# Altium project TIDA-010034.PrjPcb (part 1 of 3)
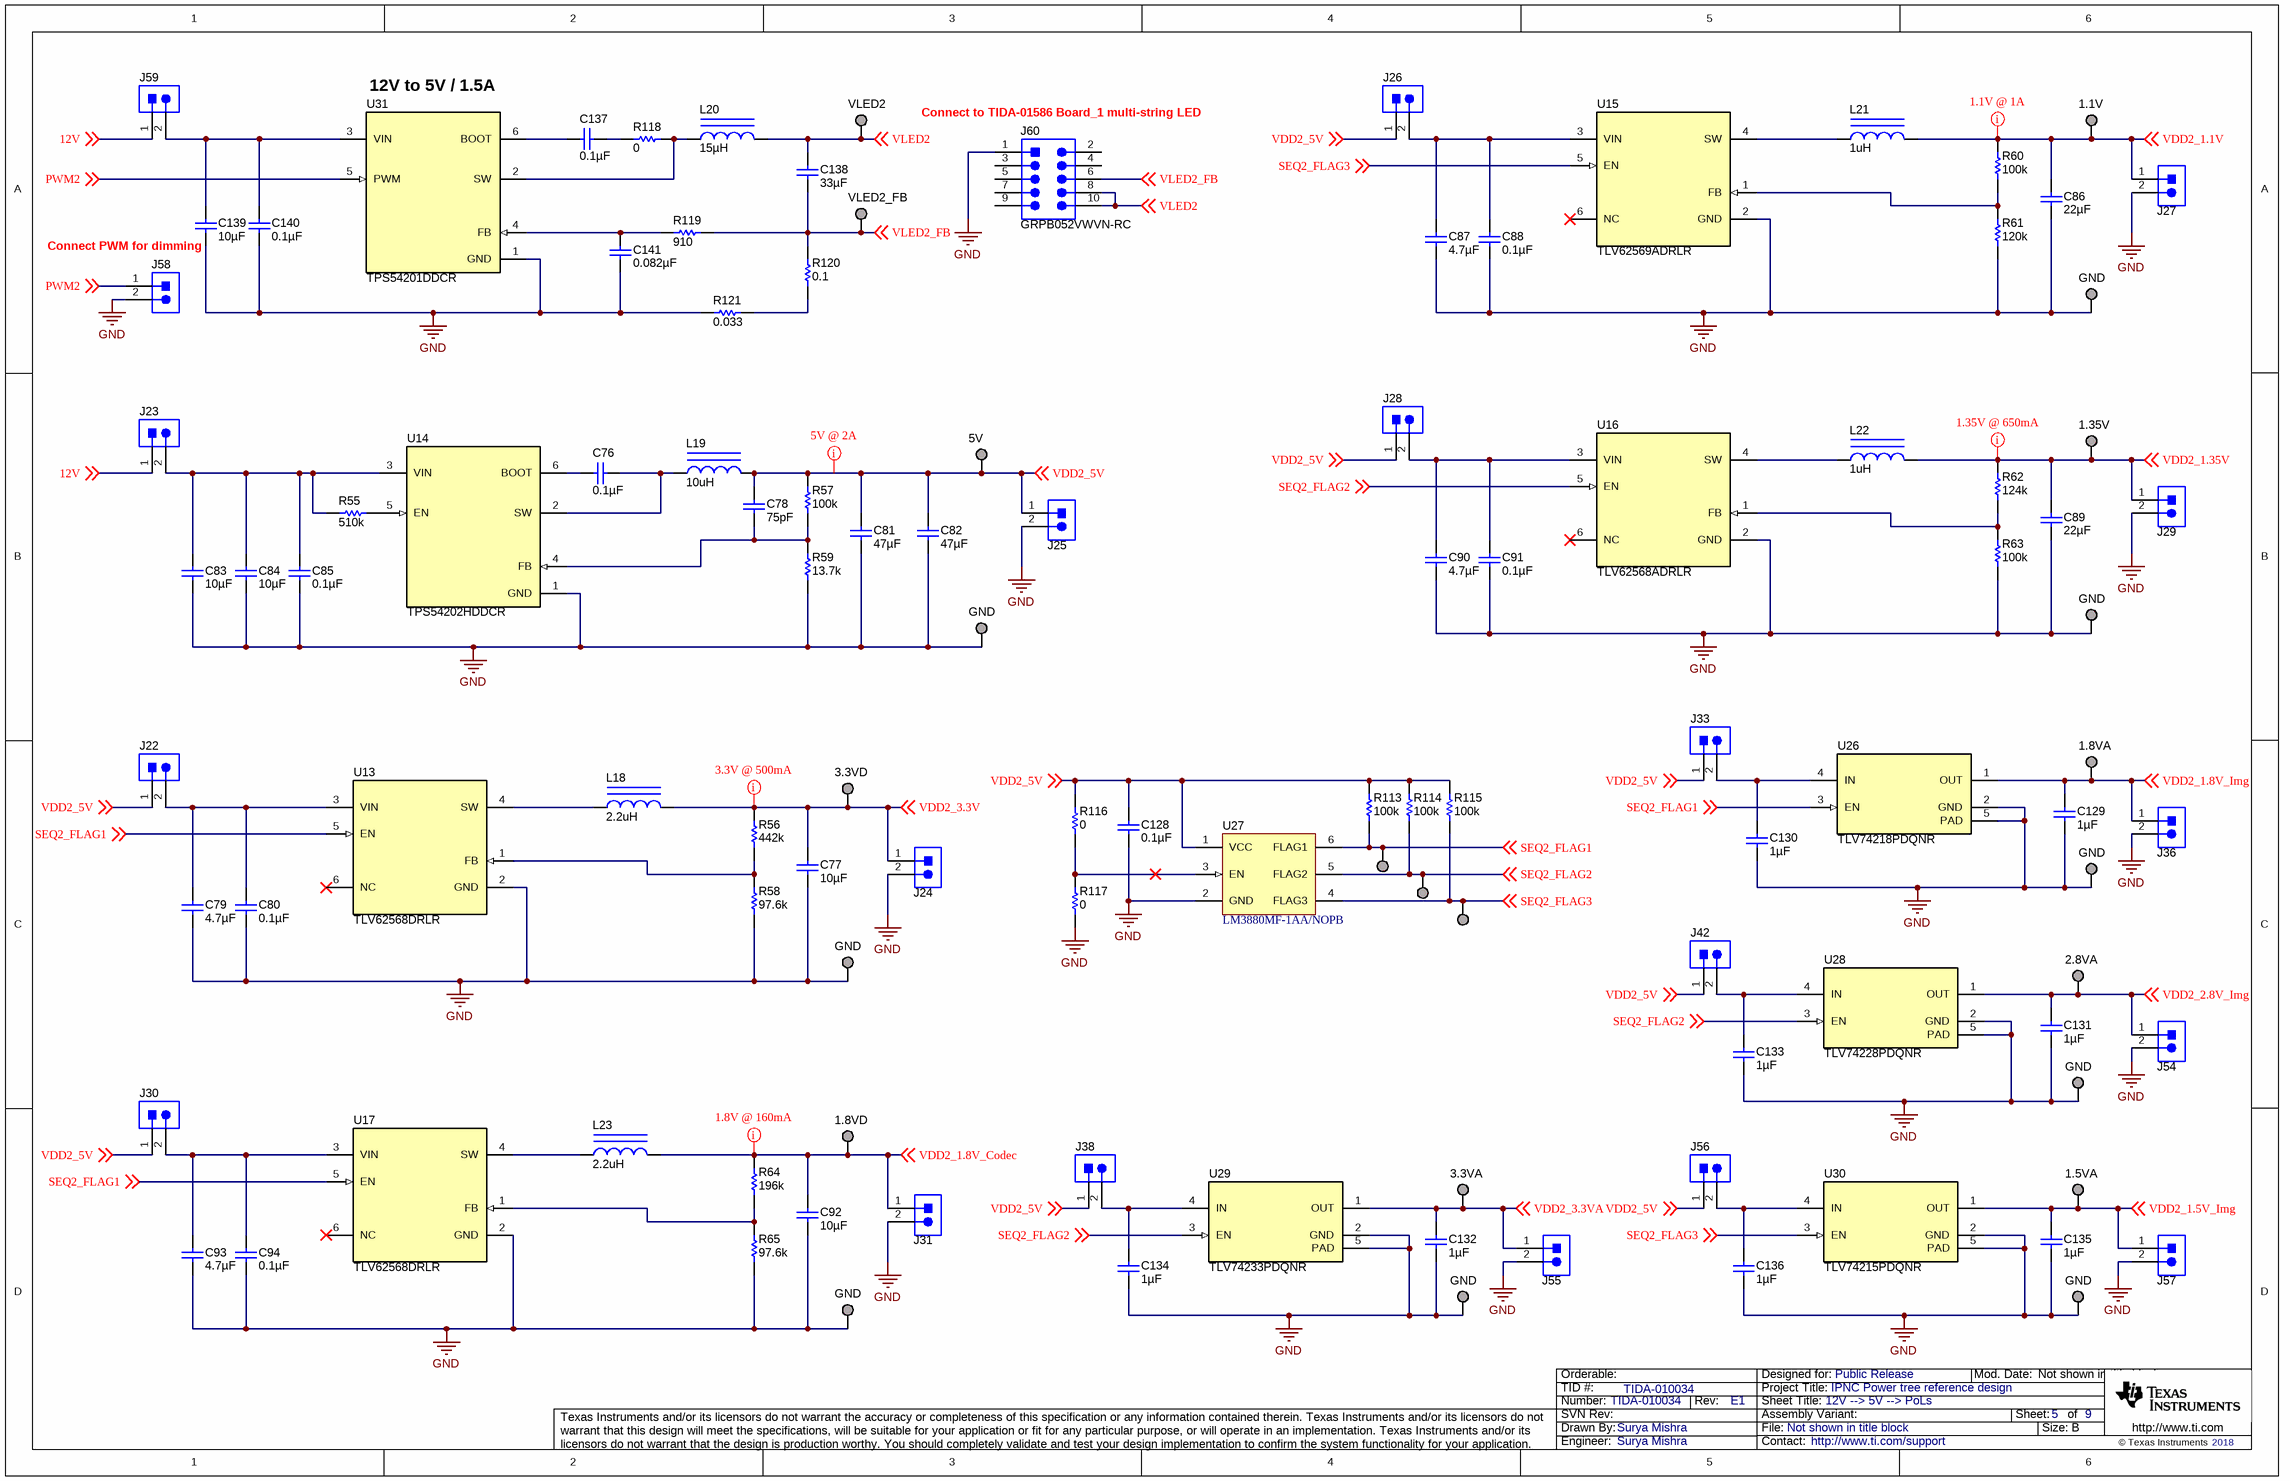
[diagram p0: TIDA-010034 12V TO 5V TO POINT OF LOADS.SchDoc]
CopyrightYear: 2018; PCB_Layout: Surya Mishra; PCB_Rev: E1; PRJ_Customer: Public Release; PRJ_Engineer: Surya Mishra; PRJ_Number: TIDA-010034; PRJ_Title: IPNC Power tree reference design; SCH_Rev: E1; TechSupport: http://www.ti.com/support; TID: TIDA-010034
9 sheets, 485 parts. Net scope: flat (ports and power ports of the same name join across sheets).
Board file: TIDA-010034 PCB.PcbDoc
Sheets:
  TIDA-010034 12V TO 5V TO POINT OF LOADS.SchDoc
  TIDA-010034 12V To POINT OF LOADS.SchDoc
  TIDA-010034 PoE INPUT.SchDoc
  TIDA-010034 USB INPUT.SchDoc
  TIDA-010034 Block Diagram.SchDoc
  TIDA-010034 TPS23755 PD FRONT-END.SchDoc
  TIDA-010034 MSP430.SchDoc
  TIDA-010034 DP83825 ETHERNET PHY.SchDoc
  TIDA-010034 Hardware.SchDoc

## Sheet TIDA-010034 12V TO 5V TO POINT OF LOADS.SchDoc: 12V --> 5V --> PoLs
size 431 x 279 mm; Date: Not shown in title block; ApprovedBy: Not shown in title block; CheckedBy: Not shown in title block; Author: Not shown in title block; CompanyName: Not shown in title block; DrawnBy: Surya Mishra; Engineer: Surya Mishra; Organization: Not shown in title block; Address1: Not shown in title block; Address2: Not shown in title block; Address3: Not shown in title block; Address4: Not shown in title block; DocumentNumber: 1; Revision: E1; SheetNumber: 5; SheetTotal: 9; PageSetup: Record=PageOptions¦CenterHorizontal=True¦CenterVertical=True¦PrintScale=1.00¦XCorrection=1.00¦YCorrection=1.00¦PrintKind=0¦BorderSize=5000000¦LeftOffset=0¦BottomOffset=0¦Orientation=2¦PaperLength=1000¦PaperWidth=1000¦Scale=100¦PaperSource=15¦PrintQuality=600¦MediaType=1¦DitherType=10¦PaperKind=Letter¦PrintScaleMode=1

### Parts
(Parts that share a designator on the sheet are numbered #1, #2 ... from top to bottom, then left to right.)
1.1V#1  TESTPOINT  [Keystone_5019]  (value not drawn)
1.5VA#1  TESTPOINT  [Keystone_5019]  (value not drawn)
1.8VA#1  TESTPOINT  [Keystone_5019]  (value not drawn)
1.8VD#1  TESTPOINT  [Keystone_5019]  (value not drawn)
1.35V#1  TESTPOINT  [Keystone_5019]  (value not drawn)
2.8VA#1  TESTPOINT  [Keystone_5019]  (value not drawn)
3.3VA#1  TESTPOINT  [Keystone_5019]  (value not drawn)
3.3VD  TESTPOINT  [Keystone_5019]  (value not drawn)
5V#1  TESTPOINT  [Keystone_5019]  (value not drawn)
C76  ValueDisplayed: 0.1µF  [0402]  (hidden comment: GRM155R71A104KA01D)
C77  ValueDisplayed: 10µF  [0805_HV]  (hidden comment: GRM21BR71A106ME51L)
C78  ValueDisplayed: 75pF  [0402]  (hidden comment: GRM1555C1H750JA01D)
C79  ValueDisplayed: 4.7µF  [0805_HV]  (hidden comment: GRM21BR71C475KA73L)
C80  ValueDisplayed: 0.1µF  [0402]  (hidden comment: GRM155R71E104KE14D)
C81  ValueDisplayed: 47µF  [1210_270]  (hidden comment: GRM32ER61C476ME15L)
C82  ValueDisplayed: 47µF  [1210_270]  (hidden comment: GRM32ER61C476ME15L)
C83  ValueDisplayed: 10µF  [0603]  (hidden comment: GRM188R61E106MA73D)
C84  ValueDisplayed: 10µF  [0603]  (hidden comment: GRM188R61E106MA73D)
C85  ValueDisplayed: 0.1µF  [0402]  (hidden comment: GRM155R71E104KE14D)
C86  ValueDisplayed: 22µF  [1206_180]  (hidden comment: GRM31CR61C226ME15L)
C87  ValueDisplayed: 4.7µF  [0805_HV]  (hidden comment: GRM21BR71C475KA73L)
C88  ValueDisplayed: 0.1µF  [0402]  (hidden comment: GRM155R71E104KE14D)
C89  ValueDisplayed: 22µF  [1206_180]  (hidden comment: GRM31CR61C226ME15L)
C90  ValueDisplayed: 4.7µF  [0805_HV]  (hidden comment: GRM21BR71C475KA73L)
C91  ValueDisplayed: 0.1µF  [0402]  (hidden comment: GRM155R71E104KE14D)
C92  ValueDisplayed: 10µF  [0805_HV]  (hidden comment: GRM21BR71A106ME51L)
C93  ValueDisplayed: 4.7µF  [0805_HV]  (hidden comment: GRM21BR71C475KA73L)
C94  ValueDisplayed: 0.1µF  [0402]  (hidden comment: GRM155R71E104KE14D)
C128  ValueDisplayed: 0.1µF  [0402]  (hidden comment: GRM155R71E104KE14D)
C129  ValueDisplayed: 1µF  [0603]  (hidden comment: GRM188R71C105KA12D)
C130  ValueDisplayed: 1µF  [0603]  (hidden comment: GRM188R71C105KA12D)
C131  ValueDisplayed: 1µF  [0603]  (hidden comment: GRM188R71C105KA12D)
C132  ValueDisplayed: 1µF  [0603]  (hidden comment: GRM188R71C105KA12D)
C133  ValueDisplayed: 1µF  [0603]  (hidden comment: GRM188R71C105KA12D)
C134  ValueDisplayed: 1µF  [0603]  (hidden comment: GRM188R71C105KA12D)
C135  ValueDisplayed: 1µF  [0603]  (hidden comment: GRM188R71C105KA12D)
C136  ValueDisplayed: 1µF  [0603]  (hidden comment: GRM188R71C105KA12D)
C137  ValueDisplayed: 0.1µF  [0402]  (hidden comment: GRM155R71A104KA01D)
C138  ValueDisplayed: 33µF  [1206_180]  (hidden comment: C3216X5R1E336M160AC)
C139  ValueDisplayed: 10µF  [0603]  (hidden comment: GRM188R61E106MA73D)
C140  ValueDisplayed: 0.1µF  [0402]  (hidden comment: GRM155R71E104KE14D)
C141  ValueDisplayed: 0.082µF  [0402]  (hidden comment: GRM155R71A823KA01D)
GND#1  TESTPOINT  [Keystone_5019]  (value not drawn)
GND#2  TESTPOINT  [Keystone_5019]  (value not drawn)
GND#3  TESTPOINT  [Keystone_5019]  (value not drawn)
GND#4  TESTPOINT  [Keystone_5019]  (value not drawn)
GND#5  TESTPOINT  [Keystone_5019]  (value not drawn)
GND#6  TESTPOINT  [Keystone_5019]  (value not drawn)
GND#7  TESTPOINT  [Keystone_5019]  (value not drawn)
GND#8  TESTPOINT  [Keystone_5019]  (value not drawn)
GND#9  TESTPOINT  [Keystone_5019]  (value not drawn)
J22  TSW-102-07-G-S  [TSW-102-07-G-S]  (value not drawn)
J23  TSW-102-07-G-S  [TSW-102-07-G-S]  (value not drawn)
J24  ED555/2DS  [TERM_BLK_ED555-2DS]  (value not drawn)
J25  ED555/2DS  [TERM_BLK_ED555-2DS]  (value not drawn)
J26  TSW-102-07-G-S  [TSW-102-07-G-S]  (value not drawn)
J27  ED555/2DS  [TERM_BLK_ED555-2DS]  (value not drawn)
J28  TSW-102-07-G-S  [TSW-102-07-G-S]  (value not drawn)
J29  ED555/2DS  [TERM_BLK_ED555-2DS]  (value not drawn)
J30  TSW-102-07-G-S  [TSW-102-07-G-S]  (value not drawn)
J31  ED555/2DS  [TERM_BLK_ED555-2DS]  (value not drawn)
J33  TSW-102-07-G-S  [TSW-102-07-G-S]  (value not drawn)
J36  ED555/2DS  [TERM_BLK_ED555-2DS]  (value not drawn)
J38  TSW-102-07-G-S  [TSW-102-07-G-S]  (value not drawn)
J42  TSW-102-07-G-S  [TSW-102-07-G-S]  (value not drawn)
J54  ED555/2DS  [TERM_BLK_ED555-2DS]  (value not drawn)
J55  ED555/2DS  [TERM_BLK_ED555-2DS]  (value not drawn)
J56  TSW-102-07-G-S  [TSW-102-07-G-S]  (value not drawn)
J57  ED555/2DS  [TERM_BLK_ED555-2DS]  (value not drawn)
J58  TSW-102-07-G-S  [TSW-102-07-G-S]  (value not drawn)
J59  TSW-102-07-G-S  [TSW-102-07-G-S]  (value not drawn)
J60  GRPB052VWVN-RC  [CONN_GRPB052VWVN-RC]
L18  ValueDisplayed: 2.2uH  [XEL4030_310]  (hidden comment: XEL4030-222MEB)
L19  ValueDisplayed: 10uH  [SRT8045]  (hidden comment: SRT8045-103MEB)
L20  ValueDisplayed: 15µH  [DEM8045C]  (hidden comment: 1217AS-H-150M=P3)
L21  ValueDisplayed: 1uH  [XEL4030_310]  (hidden comment: XEL4030-102MEB)
L22  ValueDisplayed: 1uH  [XEL4030_310]  (hidden comment: XEL4030-102MEB)
L23  ValueDisplayed: 2.2uH  [XEL4030_310]  (hidden comment: XEL4030-222MEB)
R55  ValueDisplayed: 510k  [0402]  (hidden comment: CRCW0402510KJNED)
R56  ValueDisplayed: 442k  [0402]  (hidden comment: CRCW0402442KFKED)
R57  ValueDisplayed: 100k  [0402]  (hidden comment: CRCW0402100KDHEDP)
R58  ValueDisplayed: 97.6k  [0402]  (hidden comment: CRCW040297K6FKED)
R59  ValueDisplayed: 13.7k  [0402]  (hidden comment: CRCW040213K7FKED)
R60  ValueDisplayed: 100k  [0402]  (hidden comment: CRCW0402100KDHEDP)
R61  ValueDisplayed: 120k  [0402]  (hidden comment: CRCW0402120KFKED)
R62  ValueDisplayed: 124k  [0402]  (hidden comment: CRCW0402124KFKED)
R63  ValueDisplayed: 100k  [0402]  (hidden comment: CRCW0402100KDHEDP)
R64  ValueDisplayed: 196k  [0402]  (hidden comment: CRCW0402196KFKED)
R65  ValueDisplayed: 97.6k  [0402]  (hidden comment: CRCW040297K6FKED)
R113  ValueDisplayed: 100k  [0402]  (hidden comment: CRCW0402100KJNED)
R114  ValueDisplayed: 100k  [0402]  (hidden comment: CRCW0402100KJNED)
R115  ValueDisplayed: 100k  [0402]  (hidden comment: CRCW0402100KJNED)
R116  ValueDisplayed: 0  [0402]  (hidden comment: CRCW04020000Z0ED)
R117  ValueDisplayed: 0  [0402]  (hidden comment: CRCW04020000Z0ED)
R118  ValueDisplayed: 0  [0402]  (hidden comment: CRCW04020000Z0ED)
R119  ValueDisplayed: 910  [0402]  (hidden comment: CRCW0402910RJNED)
R120  ValueDisplayed: 0.1  [1206]  (hidden comment: CSR1206FKR100)
R121  ValueDisplayed: 0.033  [1206]  (hidden comment: ERJ-8CWFR033V)
SEQ2_FLAG1  TESTPOINT  [Keystone_5019]  (value not drawn)
SEQ2_FLAG2  TESTPOINT  [Keystone_5019]  (value not drawn)
SEQ2_FLAG3  TESTPOINT  [Keystone_5019]  (value not drawn)
U13  TLV62568DRLR  [DRL0006A]
U14  TPS54202HDDCR  [DDC0006A_N]
U15  TLV62569ADRLR  [DRL0006A]
U16  TLV62568ADRLR  [DRL0006A]
U17  TLV62568DRLR  [DRL0006A]
U26  TLV74218PDQNR  [DQN0004A]
U27  LM3880MF-1AA/NOPB  [MF06A_N]
U28  TLV74228PDQNR  [DQN0004A]
U29  TLV74233PDQNR  [DQN0004A]
U30  TLV74215PDQNR  [DQN0004A]
U31  TPS54201DDCR  [DDC0006A_N]
VLED2  TESTPOINT  [Keystone_5019]  (value not drawn)
VLED2_FB  TESTPOINT  [Keystone_5019]  (value not drawn)

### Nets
GND: C77.2 C79.2 C80.2 C81.2 C82.2 C83.2 C84.2 C85.2 C86.2 C87.2 C88.2 C89.2 C90.2 C91.2 C92.2 C93.2 C94.2 C128.2 C129.2 C130.2 C131.2 C132.2 C133.2 C134.2 C135.2 C136.2 C139.2 C140.2 C141.2 GND#1.1 GND#2.1 GND#3.1 GND#4.1 GND#5.1 GND#6.1 GND#7.1 GND#8.1 GND#9.1 J24.2 J25.2 J27.2 J29.2 J31.2 J36.2 J54.2 J55.2 J57.2 J58.2 J60.1 R58.1 R59.1 R61.1 R63.1 R65.1 R117.1 R121.2 U13.2(GND) U14.1(GND) U15.2(GND) U16.2(GND) U17.2(GND) U26.2(GND) U26.5(PAD) U27.2(GND) U28.2(GND) U28.5(PAD) U29.2(GND) U29.5(PAD) U30.2(GND) U30.5(PAD) U31.1(GND)
12V: J23.1 J59.1 ; off-sheet 12V
PWM2: J58.1 U31.5(PWM) ; off-sheet PWM2
SEQ2_FLAG1: R113.1 SEQ2_FLAG1.1 U13.5(EN) U17.5(EN) U26.3(EN) U27.6(FLAG1) ; off-sheet SEQ2_FLAG1
SEQ2_FLAG2: R114.1 SEQ2_FLAG2.1 U16.5(EN) U27.5(FLAG2) U28.3(EN) U29.3(EN) ; off-sheet SEQ2_FLAG2
SEQ2_FLAG3: R115.1 SEQ2_FLAG3.1 U15.5(EN) U27.4(FLAG3) U30.3(EN) ; off-sheet SEQ2_FLAG3
VDD2_1.1V: 1.1V#1.1 C86.1 J27.1 L21.2 R60.2 ; off-sheet VDD2_1.1V
VDD2_1.5V_Img: 1.5VA#1.1 C135.1 J57.1 U30.1(OUT) ; off-sheet VDD2_1.5V_Img
VDD2_1.8V_Codec: 1.8VD#1.1 C92.1 J31.1 L23.2 R64.2 ; off-sheet VDD2_1.8V_Codec
VDD2_1.8V_Img: 1.8VA#1.1 C129.1 J36.1 U26.1(OUT) ; off-sheet VDD2_1.8V_Img
VDD2_1.35V: 1.35V#1.1 C89.1 J29.1 L22.2 R62.2 ; off-sheet VDD2_1.35V
VDD2_2.8V_Img: 2.8VA#1.1 C131.1 J54.1 U28.1(OUT) ; off-sheet VDD2_2.8V_Img
VDD2_3.3V: 3.3VD.1 C77.1 J24.1 L18.2 R56.2 ; off-sheet VDD2_3.3V
VDD2_3.3VA: 3.3VA#1.1 C132.1 J55.1 U29.1(OUT) ; off-sheet VDD2_3.3VA
VDD2_5V: 5V#1.1 C78.1 C81.1 C82.1 C128.1 J22.1 J25.1 J26.1 J28.1 J30.1 J33.1 J38.1 J42.1 J56.1 L19.2 R57.2 R113.2 R114.2 R115.2 R116.2 U27.1(VCC) ; off-sheet VDD2_5V
VLED2: C138.1 J60.8 J60.10 L20.2 VLED2.1 ; off-sheet VLED2
VLED2_FB: C138.2 J60.6 R119.2 R120.2 VLED2_FB.1 ; off-sheet VLED2_FB
NetC76_1: C76.1 L19.1 U14.2(SW)
NetC76_2: C76.2 U14.6(BOOT)
NetC78_2: C78.2 R57.1 R59.2 U14.4(FB)
NetC79_1: C79.1 C80.1 J22.2 U13.3(VIN)
NetC83_1: C83.1 C84.1 C85.1 J23.2 R55.1 U14.3(VIN)
NetC87_1: C87.1 C88.1 J26.2 U15.3(VIN)
NetC90_1: C90.1 C91.1 J28.2 U16.3(VIN)
NetC93_1: C93.1 C94.1 J30.2 U17.3(VIN)
NetC130_1: C130.1 J33.2 U26.4(IN)
NetC133_1: C133.1 J42.2 U28.4(IN)
NetC134_1: C134.1 J38.2 U29.4(IN)
NetC136_1: C136.1 J56.2 U30.4(IN)
NetC137_1: C137.1 R118.1
NetC137_2: C137.2 U31.6(BOOT)
NetC139_1: C139.1 C140.1 J59.2 U31.3(VIN)
NetC141_1: C141.1 R119.1 U31.4(FB)
NetL18_1: L18.1 U13.4(SW)
NetL20_1: L20.1 R118.2 U31.2(SW)
NetL21_1: L21.1 U15.4(SW)
NetL22_1: L22.1 U16.4(SW)
NetL23_1: L23.1 U17.4(SW)
NetR55_2: R55.2 U14.5(EN)
NetR56_1: R56.1 R58.2 U13.1(FB)
NetR60_1: R60.1 R61.2 U15.1(FB)
NetR62_1: R62.1 R63.2 U16.1(FB)
NetR64_1: R64.1 R65.2 U17.1(FB)
NetR116_1: R116.1 R117.2 U27.3(EN)
NetR120_1: R120.1 R121.1

Not connected (* = marked no-connect by the designer): J60 2 3 4 5 7 9; U13 6(NC)*; U15 6(NC)*; U16 6(NC)*; U17 6(NC)*

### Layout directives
net class Power: VDD2_1.1V, VDD2_1.8V_Codec, VDD2_1.35V, VDD2_3.3V, VDD2_5V

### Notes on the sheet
- (near U31) 12V to 5V / 1.5A
- (near J60) Connect to TIDA-01586 Board_1 multi-string LED
- (near C139) Connect PWM for dimming

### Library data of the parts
1.1V#1 1.5VA#1 1.8VA#1 1.8VD#1 1.35V#1 2.8VA#1 3.3VA#1 3.3VD 5V#1 GND#1-GND#9 SEQ2_FLAG1-SEQ2_FLAG3 VLED2 VLED2_FB = 5019: Test Point, Miniature, SMT; Manufacturer: Keystone; CompType: Test Point Loop; U/M: EA
C76 C137 = GRM155R71A104KA01D: CAP, CERM, 0.1 µF, 10 V,+/- 10%, X7R, 0402; Manufacturer: MuRata; Polarized: N; CompType: Capacitor; Value: 0.1uF; U/M: EA; Cap_F: 0.0000001; Tolerance_%: 10; Value2: 10V; TaMin_C: -55; TaMax_C: 125; SizeArea_mm2: 0.5; SizeAreaWB_mm2: 3; SizeX_mm: 1; SizeZ_mm: 0.6; AEC Category: Q200; Green_Lifecycle: Active; Green_REACh: Passed
C77 C92 = GRM21BR71A106ME51L: CAP, CERM, 10 µF, 10 V,+/- 20%, X7R, 0805; Manufacturer: MuRata; Polarized: N; CompType: Capacitor; Value: 10uF; U/M: EA; Cap_F: 0.00001; Tolerance_%: 20; VDC_V: 10; Value2: 10V; TaMin_C: -55; TaMax_C: 125; Cap_Case: 0805; SizeArea_mm2: 2.5; SizeAreaWB_mm2: 6.75; SizeX_mm: 2; SizeY_mm: 1.25; SizeZ_mm: 1.45; AEC Category: Q200; Green_Lifecycle: Active; Green_REACh: Passed
C78 = GRM1555C1H750JA01D: CAP, CERM, 75 pF, 50 V,+/- 5%, C0G/NP0, 0402; Manufacturer: MuRata; Polarized: N; CompType: Capacitor; Value: 75pF; U/M: EA; Cap_F: 0.000000000075; Tolerance_%: 5; VDC_V: 50; Value2: 50V; TaMin_C: -55; TaMax_C: 125; SizeArea_mm2: 0.5; SizeAreaWB_mm2: 3; SizeX_mm: 1; SizeZ_mm: 0.6; AEC Category: Q200
C79 C87 C90 C93 = GRM21BR71C475KA73L: CAP, CERM, 4.7 µF, 16 V,+/- 10%, X7R, 0805; Manufacturer: MuRata; Polarized: N; CompType: Capacitor; Value: 4.7uF; U/M: EA; Cap_F: 0.0000047; Tolerance_%: 10; ESR_ohm: 0.006; Value1: 0.006 ohm; VDC_V: 16; Value2: 16V; TaMin_C: -55; TaMax_C: 125; Cap_Case: 0805; SizeArea_mm2: 2.5; SizeAreaWB_mm2: 6.75; SizeX_mm: 2; SizeY_mm: 1.25; SizeZ_mm: 1.45; AEC Category: Q200; Green_Lifecycle: Active; Green_REACh: Passed
C80 C85 C88 C91 C94 C128 C140 = GRM155R71E104KE14D: CAP, CERM, 0.1 µF, 25 V,+/- 10%, X7R, 0402; Manufacturer: MuRata; Polarized: N; CompType: Capacitor; Value: 0.1uF; U/M: EA; Cap_F: 0.0000001; Tolerance_%: 10; VDC_V: 25; Value2: 25V; TaMin_C: -55; TaMax_C: 125; SizeArea_mm2: 0.5; SizeAreaWB_mm2: 3; SizeX_mm: 1; SizeZ_mm: 0.6; AEC Category: Q200; Green_Lifecycle: Active; Green_REACh: Passed
C81 C82 = GRM32ER61C476ME15L: CAP, CERM, 47 µF, 16 V,+/- 20%, X5R, 1210; Manufacturer: MuRata; Polarized: N; CompType: Capacitor; Value: 47uF; U/M: EA; Cap_F: 0.000047; Tolerance_%: 20; ESR_ohm: 0.002; Value1: 0.002 ohm; VDC_V: 16; Value2: 16V; TaMin_C: -55; TaMax_C: 85; Cap_Case: 1210; SizeArea_mm2: 8; SizeAreaWB_mm2: 14.7; SizeX_mm: 3.2; SizeY_mm: 2.5; SizeZ_mm: 2.7; AEC Category: Q200; Green_Lifecycle: Active; Green_REACh: Passed
C83 C84 C139 = GRM188R61E106MA73D: CAP, CERM, 10 µF, 25 V,+/- 20%, X5R, 0603; Manufacturer: MuRata; Polarized: N; CompType: Capacitor; Value: 10uF; U/M: EA; Cap_F: 0.00001; Tolerance_%: 20; VDC_V: 25; Value2: 25V; TaMin_C: -55; TaMax_C: 85; SizeArea_mm2: 1.28; SizeAreaWB_mm2: 4.68; SizeX_mm: 1.6; SizeY_mm: 0.8; SizeZ_mm: 1; AEC Category: Q200; Green_Lifecycle: Active; Green_REACh: Passed
C86 C89 = GRM31CR61C226ME15L: CAP, CERM, 22 µF, 16 V,+/- 20%, X5R, 1206; Manufacturer: MuRata; Polarized: N; CompType: Capacitor; Value: 22uF; U/M: EA; Cap_F: 0.000022; Tolerance_%: 20; ESR_ohm: 0.006; Value1: 0.006 ohm; VDC_V: 16; Value2: 16V; TaMin_C: -55; TaMax_C: 85; Cap_Case: 1206; SizeArea_mm2: 5.12; SizeAreaWB_mm2: 10.92; SizeX_mm: 3.2; SizeY_mm: 1.6; SizeZ_mm: 1.8; AEC Category: Q200; Green_Lifecycle: Active; Green_REACh: Passed
C129-C136 = GRM188R71C105KA12D: CAP, CERM, 1 µF, 16 V,+/- 10%, X7R, 0603; Manufacturer: MuRata; Polarized: N; CompType: Capacitor; Value: 1uF; U/M: EA; Cap_F: 0.000001; Tolerance_%: 10; ESR_ohm: 0.011; Value1: 0.011 ohm; VDC_V: 16; Value2: 16V; TaMin_C: -55; TaMax_C: 125; SizeArea_mm2: 1.28; SizeAreaWB_mm2: 4.68; SizeX_mm: 1.6; SizeY_mm: 0.8; SizeZ_mm: 1; AEC Category: Q200; Green_Lifecycle: Active; Green_REACh: Passed
C138 = C3216X5R1E336M160AC: CAP, CERM, 33 µF, 25 V,+/- 20%, X5R, 1206; Manufacturer: TDK; Polarized: N; CompType: Capacitor; Value: 33uF; U/M: EA; Cap_F: 0.000033; Tolerance_%: 20; ESR_ohm: 0.002648; Value1: 0.002648 ohm; VDC_V: 25; Value2: 25V; IRMS_A: 4.45864; TaMin_C: -55; TaMax_C: 85; Cap_Case: 1206; SizeArea_mm2: 5.12; SizeAreaWB_mm2: 10.92; SizeX_mm: 3.2; SizeY_mm: 1.6; SizeZ_mm: 1.8; AEC Category: Q200; Green_Lifecycle: Active; Green_REACh: Passed
C141 = GRM155R71A823KA01D: CAP, CERM, 0.082 µF, 10 V,+/- 10%, X7R, 0402; Manufacturer: MuRata; Polarized: N; CompType: Capacitor; Value: 0.082uF; U/M: EA; Cap_F: 0.000000082; Tolerance_%: 10; Value2: 10V; TaMin_C: -55; TaMax_C: 125; SizeArea_mm2: 0.5; SizeAreaWB_mm2: 3; SizeX_mm: 1; SizeZ_mm: 0.6; AEC Category: Q200
J22 J23 J26 J28 J30 J33 J38 J42 J56 J58 J59 = TSW-102-07-G-S: Header, 100mil, 2x1, Gold, TH; Manufacturer: Samtec; SymbolCreator: a0412235; Pitch_mm: 2.54; Gender: Male; Shrouded: N; Row_Count: 1; Current_A: 6.3; Voltage_V: 550; Cert_CSA: Y; Green_Lifecycle: Active; Green_REACh: Passed
J24 J25 J27 J29 J31 J36 J54 J55 J57 = ED555/2DS: Terminal Block, 6A, 3.5mm Pitch, 2-Pos, TH; Manufacturer: On-Shore Technology; SymbolCreator: a0412235; CompType: Connector; U/M: EA
J60 = GRPB052VWVN-RC: Header, 50mil, 5x2, Gold, TH; Manufacturer: Sullins Connector Solutions; SymbolCreator: a0412235; Green_Lifecycle: Not Set; Green_REACh: Incomplete
L18 L23 = CMP-0061088-1: Inductor, Shielded, Composite, 2.2 uH, 6.1 A, 0.0201 ohm, AEC-Q200 Grade 1, SMD; Manufacturer: Coilcraft; Isat: 6.1A @ 30% inductance drop; Irms: 7.8A @ 40C rise; SizeAreaWB_mm2: 25; DCR_ohm: 0.0201; Value: 2.2uH; Imax_A: 6.1A; SizeZ_mm: 3.1; SizeX_mm: 4; SizeArea_mm2: 16; Ind_H: 2.2µH; AEC Qualified: Y; AEC Grade: 1; AEC Category: Q200
L19 = CMP-0060942-1: Inductor, Shielded, Ferrite, 10 uH, 4.2 A, 0.037 ohm, AEC-Q200 Grade 1, SMD; Manufacturer: Coilcraft; Isat: 5.7A @ 10% inductance drop; Irms: 4.2A @ 20C rise; SizeAreaWB_mm2: 104; DCR_ohm: 0.037; Value: 10uH; Imax_A: 4.2A; SizeZ_mm: 4.6; SizeX_mm: 8; SizeY_mm: 8.4; SizeArea_mm2: 67.2; Ind_H: 10µH; AEC Qualified: Y; AEC Grade: 1; AEC Category: Q200
L20 = CMP-0084005-1: Inductor, Shielded, Ferrite, 15 µH, 3.5 A, 0.0528 ohm, SMD; Manufacturer: MuRata; Isat: 3.3A @ 30% inductance drop; Irms: 3.5A @ 40C rise; SizeAreaWB_mm2: 100; DCR_ohm: 0.0528; Value: 15uH; Imax_A: 3.5A; SizeZ_mm: 4.5; SizeX_mm: 8; SizeArea_mm2: 64; AEC Qualified: N; AEC Category: Q200
L21 L22 = CMP-0061084-1: Inductor, Shielded, Composite, 1 uH, 9 A, 0.0089 ohm, AEC-Q200 Grade 1, SMD; Manufacturer: Coilcraft; Isat: 9A @ 30% inductance drop; Irms: 10.7A @ 40C rise; SizeAreaWB_mm2: 25; DCR_ohm: 8.9m; Value: 1uH; Imax_A: 9A; SizeZ_mm: 3.1; SizeX_mm: 4; SizeArea_mm2: 16; Ind_H: 1µH; AEC Qualified: Y; AEC Grade: 1; AEC Category: Q200
R55 = CRCW0402510KJNED: RES, 510 k, 5%, 0.063 W, 0402; Manufacturer: Vishay-Dale; CompType: Resistor; Value: 510k; Res_ohm: 510000; Tolerance_%: 5; Power_W: 0.063; Value2: 0.063W; VDC_V: 50; TempCo: 200 ppm/C; SizeArea_mm2: 0.5; SizeX_mm: 1; SizeZ_mm: 0.6; EIA_Code: E24; U/M: EA; AEC Category: Q200
R56 = CRCW0402442KFKED: RES, 442 k, 1%, 0.063 W, 0402; Manufacturer: Vishay-Dale; CompType: Resistor; Value: 442k; Res_ohm: 442000; Tolerance_%: 1; Power_W: 0.063; Value2: 0.063W; VDC_V: 50; TempCo: 100 ppm/C; SizeArea_mm2: 0.5; SizeZ_mm: 0.6; EIA_Code: E96; U/M: EA; AEC Category: Q200
R57 R60 R63 = CRCW0402100KDHEDP: RES, 100 k, 0.5%, 0.063 W, 0402; Manufacturer: Vishay-Dale; CompType: Resistor; Value: 100k; Res_ohm: 100000; Tolerance_%: 0.5; Power_W: 0.063; Value2: 0.063W; VDC_V: 50; TempCo: 50 ppm/C; SizeX_mm: 1; SizeZ_mm: 0.6; EIA_Code: E192; U/M: EA; AEC Category: Q200; Green_Lifecycle: Active; Green_REACh: Passed
R58 R65 = CRCW040297K6FKED: RES, 97.6 k, 1%, 0.063 W, 0402; Manufacturer: Vishay-Dale; CompType: Resistor; Value: 97.6k; Res_ohm: 97600; Value_Code: 97k6; Tolerance_%: 1; Power_W: 0.063; Value2: 0.063W; VDC_V: 50; TempCo: 100 ppm/C; SizeArea_mm2: 0.5; SizeZ_mm: 0.6; EIA_Code: E96; U/M: EA; AEC Category: Q200
R59 = CRCW040213K7FKED: RES, 13.7 k, 1%, 0.063 W, 0402; Manufacturer: Vishay-Dale; CompType: Resistor; Value: 13.7k; Res_ohm: 13700; Value_Code: 13k7; Tolerance_%: 1; Power_W: 0.063; Value2: 0.063W; VDC_V: 50; TempCo: 100 ppm/C; SizeArea_mm2: 0.5; SizeZ_mm: 0.6; EIA_Code: E96; U/M: EA; AEC Category: Q200
R61 = CRCW0402120KFKED: RES, 120 k, 1%, 0.063 W, 0402; Manufacturer: Vishay-Dale; CompType: Resistor; Value: 120k; Res_ohm: 120000; Tolerance_%: 1; Power_W: 0.063; Value2: 0.063W; VDC_V: 50; TempCo: 100 ppm/C; SizeArea_mm2: 0.5; SizeZ_mm: 0.6; U/M: EA; AEC Category: Q200; Green_Lifecycle: Active; Green_REACh: Passed
R62 = CRCW0402124KFKED: RES, 124 k, 1%, 0.063 W, 0402; Manufacturer: Vishay-Dale; CompType: Resistor; Value: 124k; Res_ohm: 124000; Tolerance_%: 1; Power_W: 0.063; Value2: 0.063W; VDC_V: 50; TempCo: 100 ppm/C; SizeArea_mm2: 0.5; SizeZ_mm: 0.6; EIA_Code: E96; U/M: EA; AEC Category: Q200; Green_Lifecycle: Active; Green_REACh: Passed
R64 = CRCW0402196KFKED: RES, 196 k, 1%, 0.063 W, 0402; Manufacturer: Vishay-Dale; CompType: Resistor; Value: 196k; Res_ohm: 196000; Tolerance_%: 1; Power_W: 0.063; Value2: 0.063W; VDC_V: 50; TempCo: 100 ppm/C; SizeArea_mm2: 0.5; SizeZ_mm: 0.6; EIA_Code: E96; U/M: EA; AEC Category: Q200; Green_Lifecycle: Active; Green_REACh: Passed
R113-R115 = CRCW0402100KJNED: RES, 100 k, 5%, 0.063 W, 0402; Manufacturer: Vishay-Dale; CompType: Resistor; Value: 100k; Res_ohm: 100000; Tolerance_%: 5; Power_W: 0.063; Value2: 0.063W; VDC_V: 50; TempCo: 200 ppm/C; SizeArea_mm2: 0.5; SizeX_mm: 1; SizeZ_mm: 0.6; EIA_Code: E24; U/M: EA; AEC Category: Q200; Green_Lifecycle: Active; Green_REACh: Passed
R116-R118 = CRCW04020000Z0ED: RES, 0, 5%, 0.063 W, 0402; Manufacturer: Vishay-Dale; CompType: Resistor; Value: 0; Value_Code: 0000; Tolerance_%: 5; Power_W: 0.063; Value2: 0.063W; VDC_V: 50; TempCo: 200 ppm/C; SizeArea_mm2: 0.5; SizeX_mm: 1; SizeZ_mm: 0.6; EIA_Code: E24; U/M: EA; AEC Category: Q200; Green_Lifecycle: Active; Green_REACh: Passed
R119 = CRCW0402910RJNED: RES, 910, 5%, 0.063 W, 0402; Manufacturer: Vishay-Dale; CompType: Resistor; Value: 910; Value_Code: 910R; Tolerance_%: 5; Power_W: 0.063; Value2: 0.063W; VDC_V: 50; TempCo: 200 ppm/C; SizeArea_mm2: 0.5; SizeX_mm: 1; SizeZ_mm: 0.6; EIA_Code: E24; U/M: EA; AEC Category: Q200
R120 = CSR1206FKR100: RES, 0.1, 1%, 0.5 W, 1206; Manufacturer: Stackpole Electronics Inc; CompType: Resistor; Value: 0.1; Value_Code: R100; Tolerance_%: 1; Power_W: 0.5; Value2: 0.5W; TempCo: 100 ppm/C; SizeArea_mm2: 5.12; SizeX_mm: 3.2; SizeY_mm: 1.6; SizeZ_mm: 1.35; EIA_Code: E96; U/M: EA; AEC Category: Q200
R121 = ERJ-8CWFR033V: RES, 0.033, 1%, 1 W, AEC-Q200 Grade 0, 1206; Manufacturer: Panasonic; CompType: Resistor; Value: 0.033; Value_Code: R033; Tolerance_%: 1; Value2: 1W; TempCo: 50 ppm/C; SizeArea_mm2: 5.12; SizeX_mm: 3.2; SizeY_mm: 1.6; SizeZ_mm: 1.35; EIA_Code: E96; U/M: EA; AEC Category: Q200; AEC Qualified: Y; AEC Grade: 0; Green_Lifecycle: Not Set; Green_REACh: Incomplete
U13 U17 = TLV62568DRLR: 1-A High Efficiency Step-Down Converter in SOT Package, DRL0006A (SOT-OTHER-6); Alternate PartNumber: TLV62568DRLT; Manufacturer: Texas Instruments; SymbolCreator: a0411947; SizeArea_mm2: 2.56; SizeAreaWB_mm2: 6.76; SizeX_mm: 1.6; SizeZ_mm: 0.6; CompType: IC; U/M: EA
U14 = TPS54202HDDCR: 4.5-V TO 28-V INPUT, 2-A OUTPUT, EMI FRIENDLY SYNCHRONUOUS STEP-DOWN CONVERTOR, DDC0006A (SOT-23-T-6); Alternate PartNumber: TPS54202HDDCT; Manufacturer: Texas Instruments; SymbolCreator: a0411947; SizeArea_mm2: 4.8675; SizeAreaWB_mm2: 10.4675; SizeX_mm: 1.65; SizeY_mm: 2.95; SizeZ_mm: 0.87; CompType: IC; U/M: EA
U15 = CMP-0077789-1: 2-A High Efficiency Synchronous Buck Converter with Forced PWM Feature, DRL0006A (SOT-OTHER-6); Alternate PartNumber: TLV62569ADRLT; Alternate Manufacturer: Texas Instruments; SizeAreaWB_mm2: 6.76; SizeZ_mm: 0.6; SizeX_mm: 1.6; SizeArea_mm2: 2.56; CompType: IC; AEC Qualified: N; AEC Category: Q200
U16 = CMP-0081125-1: 1-A High Efficiency Synchronous Buck Converter with Forced PWM Feature, DRL0006A (SOT-OTHER-6); Alternate PartNumber: TLV62568ADRLT; Alternate Manufacturer: Texas Instruments; SizeAreaWB_mm2: 6.76; SizeZ_mm: 0.6; SizeX_mm: 1.6; SizeArea_mm2: 2.56; CompType: IC; AEC Qualified: N; AEC Category: Q200
U26 = CMP-0079107-2: 200-mA, Small Size, Low-Dropout Linear Voltage Regulator, DQN0004A (X2SON-4); Alternate Manufacturer: Texas Instruments; SizeAreaWB_mm2: 4; SizeZ_mm: 0.4; SizeX_mm: 1; CompType: IC; AEC Qualified: N; AEC Category: Q200
U27 = LM3880MF-1AA/NOPB: Power Sequencer, 6-pin SOT-23, Pb-Free; Manufacturer: Texas Instruments; PackageTopMarking: F20A*XTT; PowerWise: N; CompType: MiscPower
U28 = CMP-0079104-2: 200-mA, Small Size, Low-Dropout Linear Voltage Regulator, DQN0004A (X2SON-4); Alternate Manufacturer: Texas Instruments; SizeAreaWB_mm2: 4; SizeZ_mm: 0.4; SizeX_mm: 1; CompType: IC; AEC Qualified: N; AEC Category: Q200
U29 = CMP-0079101-2: 200-mA, Small Size, Low-Dropout Linear Voltage Regulator, DQN0004A (X2SON-4); Alternate Manufacturer: Texas Instruments; SizeAreaWB_mm2: 4; SizeZ_mm: 0.4; SizeX_mm: 1; CompType: IC; AEC Qualified: N; AEC Category: Q200
U30 = CMP-0079108-2: 200-mA, Small Size, Low-Dropout Linear Voltage Regulator, DQN0004A (X2SON-4); Alternate Manufacturer: Texas Instruments; SizeAreaWB_mm2: 4; SizeZ_mm: 0.4; SizeX_mm: 1; CompType: IC; AEC Qualified: N; AEC Category: Q200
U31 = TPS54201DDCR: 4.5V to 28V Input Voltage, Synchronous Buck LED Driver, DDC0006A (SOT-23-T-6); Alternate PartNumber: TPS54201DDCT; Manufacturer: Texas Instruments; SymbolCreator: a0412235; SizeArea_mm2: 4.8675; SizeAreaWB_mm2: 10.4675; SizeX_mm: 1.65; SizeY_mm: 2.95; SizeZ_mm: 0.87; CompType: IC; U/M: EA

## Sheet TIDA-010034 12V To POINT OF LOADS.SchDoc: 12V --> PoLs Power Tree
size 431 x 279 mm; Date: Not shown in title block; ApprovedBy: Not shown in title block; CheckedBy: Not shown in title block; Author: Not shown in title block; CompanyName: Not shown in title block; DrawnBy: Surya Mishra; Engineer: Surya Mishra; Organization: Not shown in title block; Address1: Not shown in title block; Address2: Not shown in title block; Address3: Not shown in title block; Address4: Not shown in title block; DocumentNumber: 1; Revision: E1; SheetNumber: 4; SheetTotal: 9; PageSetup: Record=PageOptions¦CenterHorizontal=True¦CenterVertical=True¦PrintScale=1.00¦XCorrection=1.00¦YCorrection=1.00¦PrintKind=0¦BorderSize=5000000¦LeftOffset=0¦BottomOffset=0¦Orientation=2¦PaperLength=1000¦PaperWidth=1000¦Scale=100¦PaperSource=15¦PrintQuality=600¦MediaType=1¦DitherType=10¦PaperKind=Letter¦PrintScaleMode=1
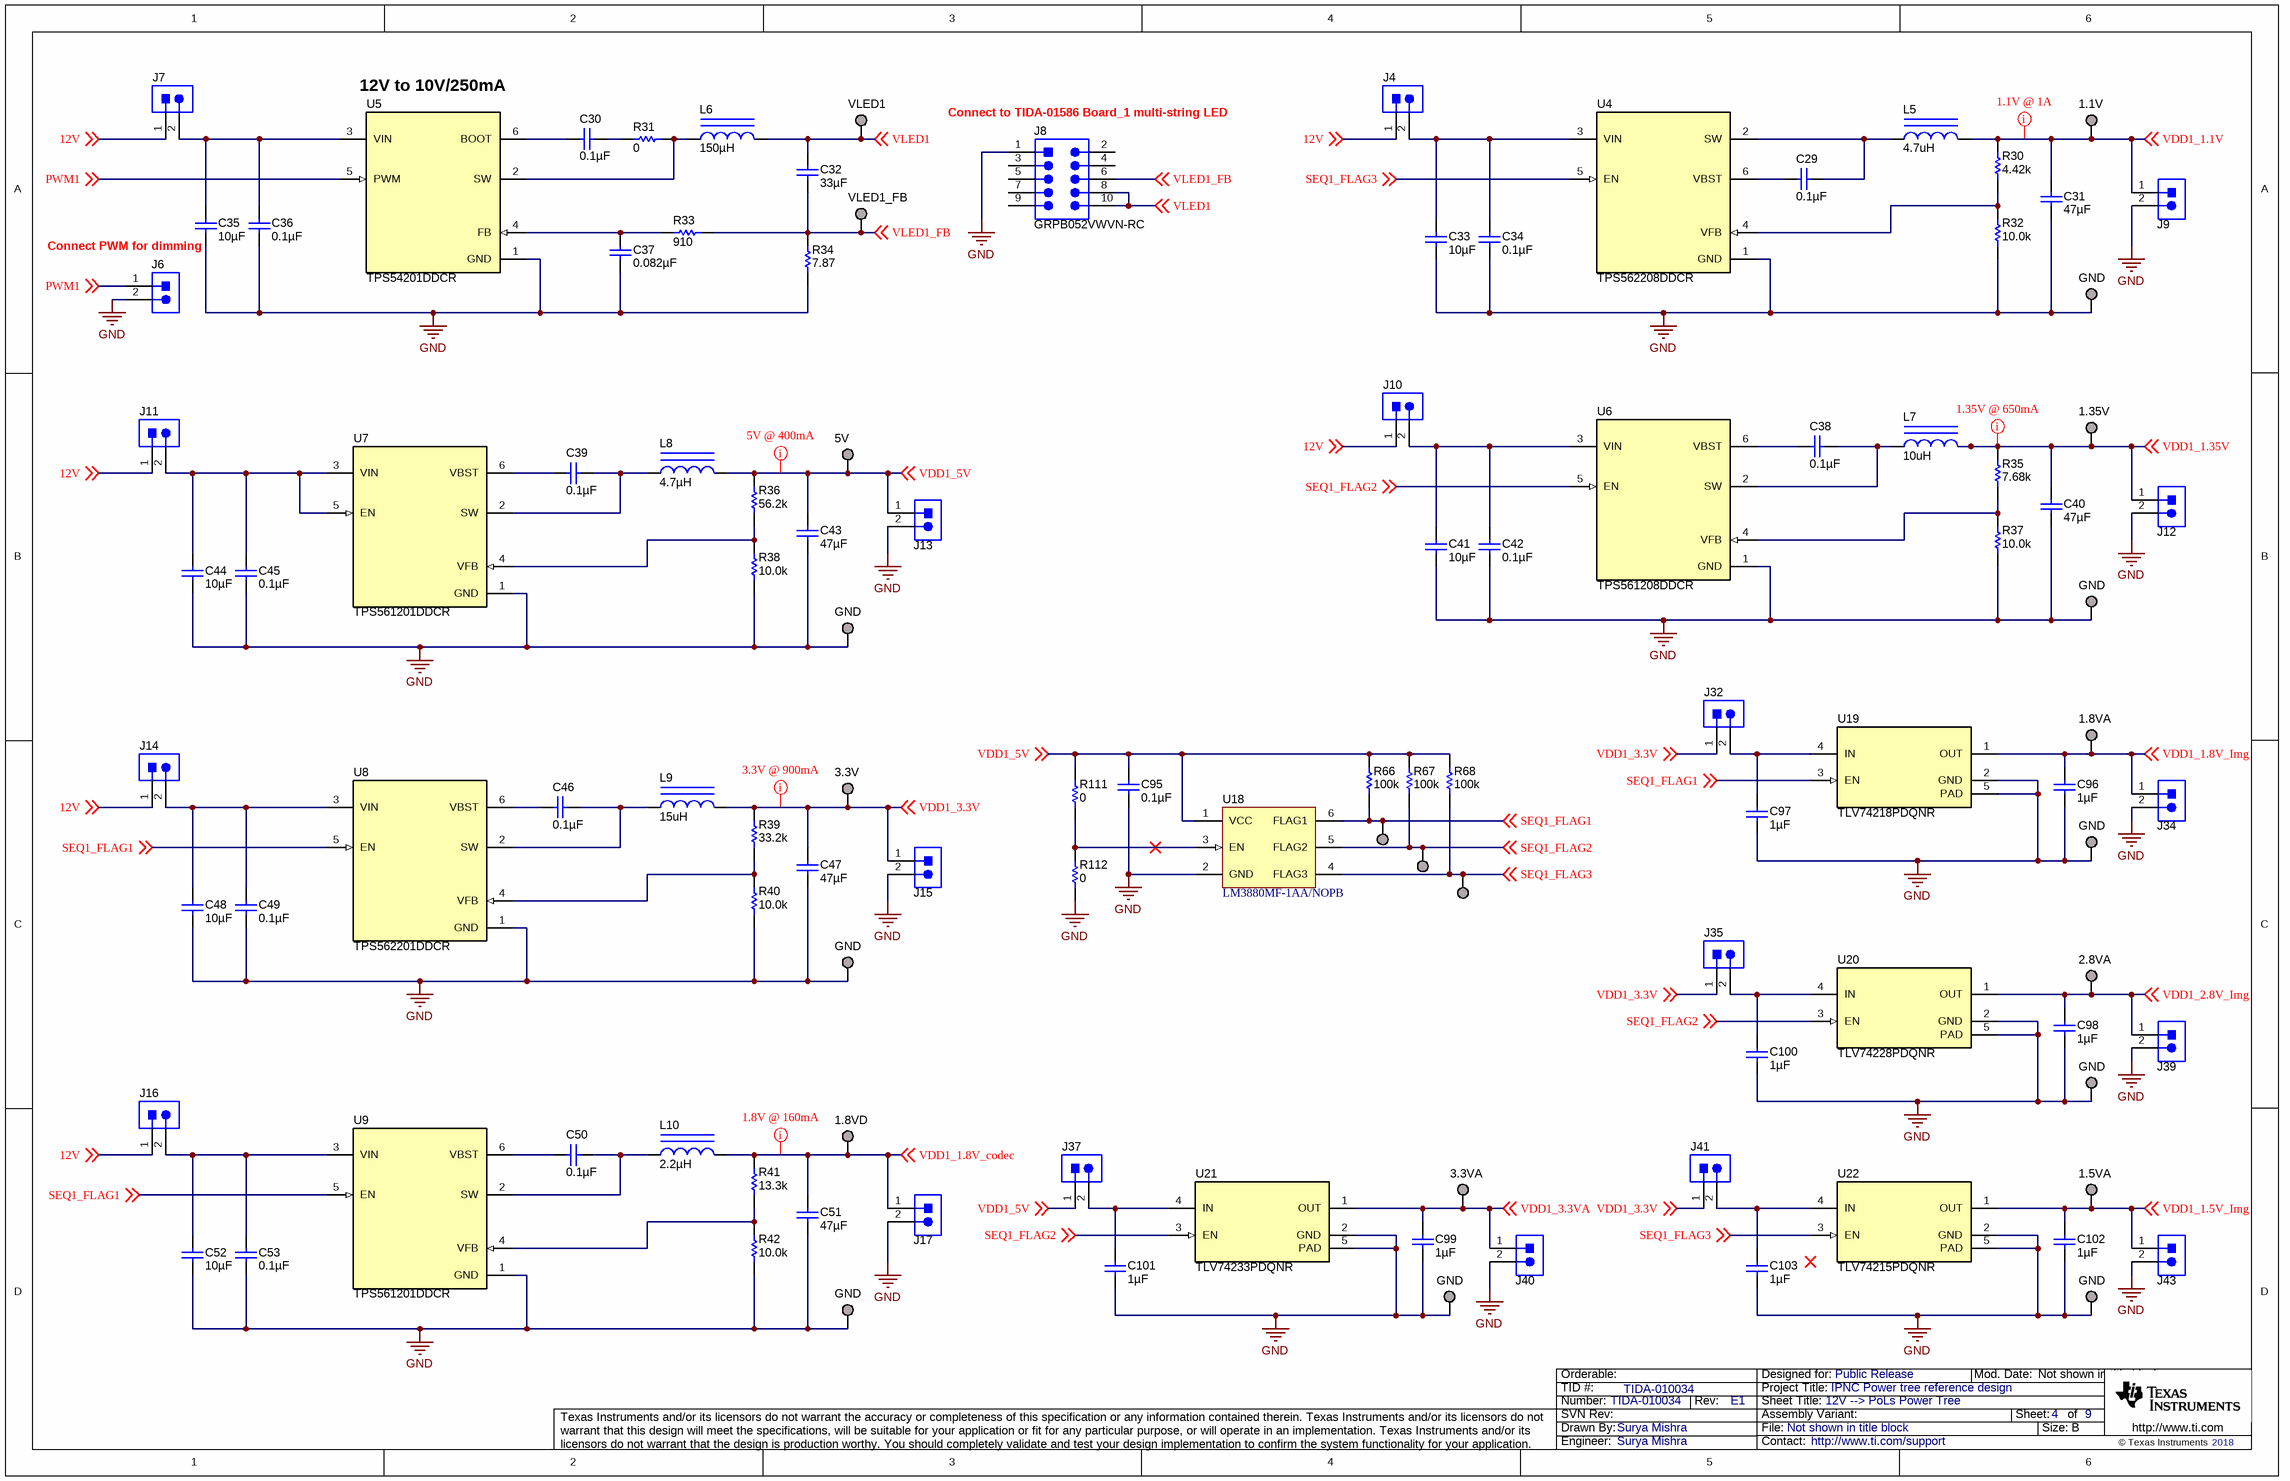
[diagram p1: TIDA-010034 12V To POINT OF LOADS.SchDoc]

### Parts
(Parts that share a designator on the sheet are numbered #1, #2 ... from top to bottom, then left to right.)
1.1V#2  TESTPOINT  [Keystone_5019]  (value not drawn)
1.5VA#2  TESTPOINT  [Keystone_5019]  (value not drawn)
1.8VA#2  TESTPOINT  [Keystone_5019]  (value not drawn)
1.8VD#2  TESTPOINT  [Keystone_5019]  (value not drawn)
1.35V#2  TESTPOINT  [Keystone_5019]  (value not drawn)
2.8VA#2  TESTPOINT  [Keystone_5019]  (value not drawn)
3.3V  TESTPOINT  [Keystone_5019]  (value not drawn)
3.3VA#2  TESTPOINT  [Keystone_5019]  (value not drawn)
5V#2  TESTPOINT  [Keystone_5019]  (value not drawn)
C29  ValueDisplayed: 0.1µF  [0402]  (hidden comment: GRM155R71A104KA01D)
C30  ValueDisplayed: 0.1µF  [0402]  (hidden comment: GRM155R71A104KA01D)
C31  ValueDisplayed: 47µF  [0805_HV]  (hidden comment: C2012X5R1A476M125AC)
C32  ValueDisplayed: 33µF  [1206_180]  (hidden comment: C3216X5R1E336M160AC)
C33  ValueDisplayed: 10µF  [0603]  (hidden comment: GRM188R61E106MA73D)
C34  ValueDisplayed: 0.1µF  [0402]  (hidden comment: GRM155R71E104KE14D)
C35  ValueDisplayed: 10µF  [0603]  (hidden comment: GRM188R61E106MA73D)
C36  ValueDisplayed: 0.1µF  [0402]  (hidden comment: GRM155R71E104KE14D)
C37  ValueDisplayed: 0.082µF  [0402]  (hidden comment: GRM155R71A823KA01D)
C38  ValueDisplayed: 0.1µF  [0402]  (hidden comment: GRM155R71A104KA01D)
C39  ValueDisplayed: 0.1µF  [0402]  (hidden comment: GRM155R71A104KA01D)
C40  ValueDisplayed: 47µF  [0805_HV]  (hidden comment: C2012X5R1A476M125AC)
C41  ValueDisplayed: 10µF  [0603]  (hidden comment: GRM188R61E106MA73D)
C42  ValueDisplayed: 0.1µF  [0402]  (hidden comment: GRM155R71E104KE14D)
C43  ValueDisplayed: 47µF  [1210_270]  (hidden comment: GRM32ER61C476ME15L)
C44  ValueDisplayed: 10µF  [0603]  (hidden comment: GRM188R61E106MA73D)
C45  ValueDisplayed: 0.1µF  [0402]  (hidden comment: GRM155R71E104KE14D)
C46  ValueDisplayed: 0.1µF  [0402]  (hidden comment: GRM155R71A104KA01D)
C47  ValueDisplayed: 47µF  [0805_HV]  (hidden comment: C2012X5R1A476M125AC)
C48  ValueDisplayed: 10µF  [0603]  (hidden comment: GRM188R61E106MA73D)
C49  ValueDisplayed: 0.1µF  [0402]  (hidden comment: GRM155R71E104KE14D)
C50  ValueDisplayed: 0.1µF  [0402]  (hidden comment: GRM155R71A104KA01D)
C51  ValueDisplayed: 47µF  [0805_HV]  (hidden comment: C2012X5R1A476M125AC)
C52  ValueDisplayed: 10µF  [0603]  (hidden comment: GRM188R61E106MA73D)
C53  ValueDisplayed: 0.1µF  [0402]  (hidden comment: GRM155R71E104KE14D)
C95  ValueDisplayed: 0.1µF  [0402]  (hidden comment: GRM155R71E104KE14D)
C96  ValueDisplayed: 1µF  [0402]  (hidden comment: GRM155R61A105KE15D)
C97  ValueDisplayed: 1µF  [0402]  (hidden comment: GRM155R61A105KE15D)
C98  ValueDisplayed: 1µF  [0402]  (hidden comment: GRM155R61A105KE15D)
C99  ValueDisplayed: 1µF  [0603]  (hidden comment: GRM188R71C105KA12D)
C100  ValueDisplayed: 1µF  [0402]  (hidden comment: GRM155R61A105KE15D)
C101  ValueDisplayed: 1µF  [0603]  (hidden comment: GRM188R71C105KA12D)
C102  ValueDisplayed: 1µF  [0402]  (hidden comment: GRM155R61A105KE15D)
C103  ValueDisplayed: 1µF  [0402]  (hidden comment: GRM155R61A105KE15D)
GND#10  TESTPOINT  [Keystone_5019]  (value not drawn)
GND#11  TESTPOINT  [Keystone_5019]  (value not drawn)
GND#12  TESTPOINT  [Keystone_5019]  (value not drawn)
GND#13  TESTPOINT  [Keystone_5019]  (value not drawn)
GND#14  TESTPOINT  [Keystone_5019]  (value not drawn)
GND#15  TESTPOINT  [Keystone_5019]  (value not drawn)
GND#16  TESTPOINT  [Keystone_5019]  (value not drawn)
GND#17  TESTPOINT  [Keystone_5019]  (value not drawn)
GND#18  TESTPOINT  [Keystone_5019]  (value not drawn)
J4  TSW-102-07-G-S  [TSW-102-07-G-S]  (value not drawn)
J6  TSW-102-07-G-S  [TSW-102-07-G-S]  (value not drawn)
J7  TSW-102-07-G-S  [TSW-102-07-G-S]  (value not drawn)
J8  GRPB052VWVN-RC  [CONN_GRPB052VWVN-RC]
J9  ED555/2DS  [TERM_BLK_ED555-2DS]  (value not drawn)
J10  TSW-102-07-G-S  [TSW-102-07-G-S]  (value not drawn)
J11  TSW-102-07-G-S  [TSW-102-07-G-S]  (value not drawn)
J12  ED555/2DS  [TERM_BLK_ED555-2DS]  (value not drawn)
J13  ED555/2DS  [TERM_BLK_ED555-2DS]  (value not drawn)
J14  TSW-102-07-G-S  [TSW-102-07-G-S]  (value not drawn)
J15  ED555/2DS  [TERM_BLK_ED555-2DS]  (value not drawn)
J16  TSW-102-07-G-S  [TSW-102-07-G-S]  (value not drawn)
J17  ED555/2DS  [TERM_BLK_ED555-2DS]  (value not drawn)
J32  TSW-102-07-G-S  [TSW-102-07-G-S]  (value not drawn)
J34  ED555/2DS  [TERM_BLK_ED555-2DS]  (value not drawn)
J35  TSW-102-07-G-S  [TSW-102-07-G-S]  (value not drawn)
J37  TSW-102-07-G-S  [TSW-102-07-G-S]  (value not drawn)
J39  ED555/2DS  [TERM_BLK_ED555-2DS]  (value not drawn)
J40  ED555/2DS  [TERM_BLK_ED555-2DS]  (value not drawn)
J41  TSW-102-07-G-S  [TSW-102-07-G-S]  (value not drawn)
J43  ED555/2DS  [TERM_BLK_ED555-2DS]  (value not drawn)
L5  ValueDisplayed: 4.7uH  [LQH5BPN_38]  (hidden comment: LQH5BPN4R7N38L)
L6  ValueDisplayed: 150µH  [LPS8045B]  (hidden comment: LPS8045B-154MRB)
L7  ValueDisplayed: 10uH  [IND_1255AY]  (hidden comment: 1255AY-100M=P3)
L8  ValueDisplayed: 4.7µH  [XFL5030]  (hidden comment: XFL5030-472MEC)
L9  ValueDisplayed: 15uH  [SRT8045]  (hidden comment: SRT8045-103MEB)
L10  ValueDisplayed: 2.2µH  [XFL5030]  (hidden comment: XFL5030-472MEC)
R30  ValueDisplayed: 4.42k  [0402]  (hidden comment: CRCW04024K42FKED)
R31  ValueDisplayed: 0  [0402]  (hidden comment: CRCW04020000Z0ED)
R32  ValueDisplayed: 10.0k  [0402]  (hidden comment: CRCW040210K0FKED)
R33  ValueDisplayed: 910  [0402]  (hidden comment: CRCW0402910RJNED)
R34  ValueDisplayed: 7.87  [1206]  (hidden comment: CRCW12067R87FKEA)
R35  ValueDisplayed: 7.68k  [0402]  (hidden comment: CRCW04027K68FKED)
R36  ValueDisplayed: 56.2k  [0402]  (hidden comment: CRCW040256K2FKED)
R37  ValueDisplayed: 10.0k  [0402]  (hidden comment: CRCW040210K0FKED)
R38  ValueDisplayed: 10.0k  [0402]  (hidden comment: CRCW040210K0FKED)
R39  ValueDisplayed: 33.2k  [0402]  (hidden comment: CRCW040233K2FKED)
R40  ValueDisplayed: 10.0k  [0402]  (hidden comment: CRCW040210K0FKED)
R41  ValueDisplayed: 13.3k  [0402]  (hidden comment: CRCW040213K3FKED)
R42  ValueDisplayed: 10.0k  [0402]  (hidden comment: CRCW040210K0FKED)
R66  ValueDisplayed: 100k  [0402]  (hidden comment: CRCW0402100KJNED)
R67  ValueDisplayed: 100k  [0402]  (hidden comment: CRCW0402100KJNED)
R68  ValueDisplayed: 100k  [0402]  (hidden comment: CRCW0402100KJNED)
R111  ValueDisplayed: 0  [0402]  (hidden comment: CRCW04020000Z0ED)
R112  ValueDisplayed: 0  [0402]  (hidden comment: CRCW04020000Z0ED)
SEQ1_FLAG1  TESTPOINT  [Keystone_5019]  (value not drawn)
SEQ1_FLAG2  TESTPOINT  [Keystone_5019]  (value not drawn)
SEQ1_FLAG3  TESTPOINT  [Keystone_5019]  (value not drawn)
U4  TPS562208DDCR  [DDC0006A_N]
U5  TPS54201DDCR  [DDC0006A_N]
U6  TPS561208DDCR  [DDC0006A_N]
U7  TPS561201DDCR  [DDC0006A_N]
U8  TPS562201DDCR  [DDC0006A_N]
U9  TPS561201DDCR  [DDC0006A_N]
U18  LM3880MF-1AA/NOPB  [MF06A_N]
U19  TLV74218PDQNR  [DQN0004A]
U20  TLV74228PDQNR  [DQN0004A]
U21  TLV74233PDQNR  [DQN0004A]
U22  TLV74215PDQNR  [DQN0004A]
VLED1  TESTPOINT  [Keystone_5019]  (value not drawn)
VLED1_FB  TESTPOINT  [Keystone_5019]  (value not drawn)

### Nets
GND: C31.2 C33.2 C34.2 C35.2 C36.2 C37.2 C40.2 C41.2 C42.2 C43.2 C44.2 C45.2 C47.2 C48.2 C49.2 C51.2 C52.2 C53.2 C95.2 C96.2 C97.2 C98.2 C99.2 C100.2 C101.2 C102.2 C103.2 GND#10.1 GND#11.1 GND#12.1 GND#13.1 GND#14.1 GND#15.1 GND#16.1 GND#17.1 GND#18.1 J6.2 J8.1 J9.2 J12.2 J13.2 J15.2 J17.2 J34.2 J39.2 J40.2 J43.2 R32.1 R34.1 R37.1 R38.1 R40.1 R42.1 R112.1 U4.1(GND) U5.1(GND) U6.1(GND) U7.1(GND) U8.1(GND) U9.1(GND) U18.2(GND) U19.2(GND) U19.5(PAD) U20.2(GND) U20.5(PAD) U21.2(GND) U21.5(PAD) U22.2(GND) U22.5(PAD)
12V: J4.1 J7.1 J10.1 J11.1 J14.1 J16.1 ; off-sheet 12V
PWM1: J6.1 U5.5(PWM) ; off-sheet PWM1
SEQ1_FLAG1: R66.1 SEQ1_FLAG1.1 U8.5(EN) U9.5(EN) U18.6(FLAG1) U19.3(EN) ; off-sheet SEQ1_FLAG1
SEQ1_FLAG2: R67.1 SEQ1_FLAG2.1 U6.5(EN) U18.5(FLAG2) U20.3(EN) U21.3(EN) ; off-sheet SEQ1_FLAG2
SEQ1_FLAG3: R68.1 SEQ1_FLAG3.1 U4.5(EN) U18.4(FLAG3) U22.3(EN) ; off-sheet SEQ1_FLAG3
VDD1_1.1V: 1.1V#2.1 C31.1 J9.1 L5.2 R30.2 ; off-sheet VDD1_1.1V
VDD1_1.5V_Img: 1.5VA#2.1 C102.1 J43.1 U22.1(OUT) ; off-sheet VDD1_1.5V_Img
VDD1_1.8V_codec: 1.8VD#2.1 C51.1 J17.1 L10.2 R41.2 ; off-sheet VDD1_1.8V_codec
VDD1_1.8V_Img: 1.8VA#2.1 C96.1 J34.1 U19.1(OUT) ; off-sheet VDD1_1.8V_Img
VDD1_1.35V: 1.35V#2.1 C40.1 J12.1 L7.2 R35.2 ; off-sheet VDD1_1.35V
VDD1_2.8V_Img: 2.8VA#2.1 C98.1 J39.1 U20.1(OUT) ; off-sheet VDD1_2.8V_Img
VDD1_3.3V: 3.3V.1 C47.1 J15.1 J32.1 J35.1 J41.1 L9.2 R39.2 ; off-sheet VDD1_3.3V
VDD1_3.3VA: 3.3VA#2.1 C99.1 J40.1 U21.1(OUT) ; off-sheet VDD1_3.3VA
VDD1_5V: 5V#2.1 C43.1 C95.1 J13.1 J37.1 L8.2 R36.2 R66.2 R67.2 R68.2 R111.2 U18.1(VCC) ; off-sheet VDD1_5V
VLED1: C32.1 J8.8 J8.10 L6.2 VLED1.1 ; off-sheet VLED1
VLED1_FB: C32.2 J8.6 R33.2 R34.2 VLED1_FB.1 ; off-sheet VLED1_FB
NetC29_1: C29.1 L5.1 U4.2(SW)
NetC29_2: C29.2 U4.6(VBST)
NetC30_1: C30.1 R31.1
NetC30_2: C30.2 U5.6(BOOT)
NetC33_1: C33.1 C34.1 J4.2 U4.3(VIN)
NetC35_1: C35.1 C36.1 J7.2 U5.3(VIN)
NetC37_1: C37.1 R33.1 U5.4(FB)
NetC38_1: C38.1 L7.1 U6.2(SW)
NetC38_2: C38.2 U6.6(VBST)
NetC39_1: C39.1 L8.1 U7.2(SW)
NetC39_2: C39.2 U7.6(VBST)
NetC41_1: C41.1 C42.1 J10.2 U6.3(VIN)
NetC44_1: C44.1 C45.1 J11.2 U7.3(VIN) U7.5(EN)
NetC46_1: C46.1 L9.1 U8.2(SW)
NetC46_2: C46.2 U8.6(VBST)
NetC48_1: C48.1 C49.1 J14.2 U8.3(VIN)
NetC50_1: C50.1 L10.1 U9.2(SW)
NetC50_2: C50.2 U9.6(VBST)
NetC52_1: C52.1 C53.1 J16.2 U9.3(VIN)
NetC97_1: C97.1 J32.2 U19.4(IN)
NetC100_1: C100.1 J35.2 U20.4(IN)
NetC101_1: C101.1 J37.2 U21.4(IN)
NetC103_1: C103.1 J41.2 U22.4(IN)
NetL6_1: L6.1 R31.2 U5.2(SW)
NetR30_1: R30.1 R32.2 U4.4(VFB)
NetR35_1: R35.1 R37.2 U6.4(VFB)
NetR36_1: R36.1 R38.2 U7.4(VFB)
NetR39_1: R39.1 R40.2 U8.4(VFB)
NetR41_1: R41.1 R42.2 U9.4(VFB)
NetR111_1: R111.1 R112.2 U18.3(EN)

Not connected (* = marked no-connect by the designer): J8 2 3 4 5 7 9

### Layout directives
net class Power: VDD1_1.1V, VDD1_1.8V_codec, VDD1_1.35V, VDD1_3.3V, VDD1_5V

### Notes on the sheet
- (near U5) 12V to 10V/250mA
- (near J8) Connect to TIDA-01586 Board_1 multi-string LED
- (near C35) Connect PWM for dimming

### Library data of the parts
1.1V#2 1.5VA#2 1.8VA#2 1.8VD#2 1.35V#2 2.8VA#2 3.3V 3.3VA#2 5V#2 GND#10-GND#18 SEQ1_FLAG1-SEQ1_FLAG3 VLED1 VLED1_FB = 5019: as 1.1V#1 on sheet TIDA-010034 12V TO 5V TO POINT OF LOADS
C29 C30 C38 C39 C46 C50 = GRM155R71A104KA01D: as C76 on sheet TIDA-010034 12V TO 5V TO POINT OF LOADS
C31 C40 C47 C51 = C2012X5R1A476M125AC: CAP, CERM, 47 µF, 10 V,+/- 20%, X5R, 0805; Manufacturer: TDK; Polarized: N; CompType: Capacitor; Value: 47uF; U/M: EA; Cap_F: 0.000047; Tolerance_%: 20; ESR_ohm: 0.00294; Value1: 0.00294 ohm; VDC_V: 10; Value2: 10V; IRMS_A: 3.80451; TaMin_C: -55; TaMax_C: 85; Cap_Case: 0805; SizeArea_mm2: 2.5; SizeAreaWB_mm2: 6.75; SizeX_mm: 2; SizeY_mm: 1.25; SizeZ_mm: 1.45; AEC Category: Q200; Green_Lifecycle: Active; Green_REACh: Passed
C32 = C3216X5R1E336M160AC: as C138 on sheet TIDA-010034 12V TO 5V TO POINT OF LOADS
C33 C35 C41 C44 C48 C52 = GRM188R61E106MA73D: as C83 on sheet TIDA-010034 12V TO 5V TO POINT OF LOADS
C34 C36 C42 C45 C49 C53 C95 = GRM155R71E104KE14D: as C80 on sheet TIDA-010034 12V TO 5V TO POINT OF LOADS
C37 = GRM155R71A823KA01D: as C141 on sheet TIDA-010034 12V TO 5V TO POINT OF LOADS
C43 = GRM32ER61C476ME15L: as C81 on sheet TIDA-010034 12V TO 5V TO POINT OF LOADS
C96-C98 C100 C102 C103 = GRM155R61A105KE15D: CAP, CERM, 1 µF, 10 V,+/- 10%, X5R, 0402; Manufacturer: MuRata; Polarized: N; CompType: Capacitor; Value: 1uF; U/M: EA; Cap_F: 0.000001; Tolerance_%: 10; Value2: 10V; TaMin_C: -55; TaMax_C: 85; SizeArea_mm2: 0.5; SizeAreaWB_mm2: 3; SizeX_mm: 1; SizeZ_mm: 0.6; AEC Category: Q200; Green_Lifecycle: Active; Green_REACh: Passed
C99 C101 = GRM188R71C105KA12D: as C129 on sheet TIDA-010034 12V TO 5V TO POINT OF LOADS
J4 J6 J7 J10 J11 J14 J16 J32 J35 J37 J41 = TSW-102-07-G-S: as J22 on sheet TIDA-010034 12V TO 5V TO POINT OF LOADS
J8 = GRPB052VWVN-RC: as J60 on sheet TIDA-010034 12V TO 5V TO POINT OF LOADS
J9 J12 J13 J15 J17 J34 J39 J40 J43 = ED555/2DS: as J24 on sheet TIDA-010034 12V TO 5V TO POINT OF LOADS
L5 = CMP-0058729-1: Inductor, Wirewound, Ferrite, 4.7 uH, 3.5 A, 0.0312 ohm, SMD; Manufacturer: MuRata; Isat: 3.5A @ 30% inductance drop; Irms: 3.8A @ 40C rise; SizeAreaWB_mm2: 34.81; DCR_ohm: 0.0312; Value: 4.7uH; Imax_A: 3.5A; SizeZ_mm: 4; SizeX_mm: 4.9; SizeArea_mm2: 24.01; Ind_H: 4.7µH; AEC Qualified: N; AEC Category: Q200
L6 = CMP-0080680-2: Inductor, Shielded, Ferrite, 150 µH, 0.95 A, 0.379 ohm, SMD; Manufacturer: Coilcraft; Isat: 0.95A @ 30% inductance drop; Irms: 0.95A @ 40C rise; Green_Lifecycle: Active; SizeAreaWB_mm2: 101.525776; DCR_ohm: 0.379; Green_REACh: Incomplete; Value: 150uH; Imax_A: 950mA; SizeZ_mm: 4.7; SizeX_mm: 8.076; Value2: 0.95A; SizeArea_mm2: 65.221776; AEC Qualified: N; AEC Category: Q200
L7 = CMP-0058569-1: Inductor, Shielded, Ferrite, 10 uH, 2.9 A, 0.0564 ohm, SMD; Manufacturer: MuRata; Isat: 3.1A @ 30% inductance drop; Irms: 2.9A @ 40C rise; SizeAreaWB_mm2: 68.89; DCR_ohm: 0.0564; Value: 10uH; Imax_A: 2.9A; SizeZ_mm: 4.5; SizeX_mm: 6.3; SizeArea_mm2: 39.69; Ind_H: 10µH; AEC Qualified: N; AEC Category: Q200
L8 = CMP-0076756-1: Inductor, Shielded, Composite, 4.7 µH, 2.5 A, 0.022 ohm, AEC-Q200 Grade 1, SMD; Manufacturer: Coilcraft; SizeAreaWB_mm2: 54.4544; Irms: 8.7A @ 40C rise; SizeArea_mm2: 28.9344; AEC Qualified: Y; AEC Category: Q200; Value: 4.7uH; SizeZ_mm: 3.1; Imax_A: 2.5A; AEC Grade: 1; SizeY_mm: 5.28; Isat: 2.5A @ 10% inductance drop; DCR_ohm: 0.022; SizeX_mm: 5.48
L9 = CMP-0060942-1: Inductor, Shielded, Ferrite, 15 uH, 4 A, 0.048 ohm, AEC-Q200 Grade 1, SMD; Manufacturer: Coilcraft; PartNumber: SRT8045-153MEB; Isat: 5.7A @ 10% inductance drop; Irms: 4A @ 20C rise; SizeAreaWB_mm2: 104; DCR_ohm: 0.048; Value: 15uH; Imax_A: 4A; SizeZ_mm: 4.6; SizeX_mm: 8; SizeY_mm: 8.4; SizeArea_mm2: 67.2; Ind_H: 15µH; AEC Qualified: Y; AEC Grade: 1; AEC Category: Q200
L10 = CMP-0076756-1: Inductor, Shielded, Composite, 2.2 µH, 3.5 A, 0.012 ohm, AEC-Q200 Grade 1, SMD; PartNumber: XFL5030-222; Manufacturer: Coilcraft; SizeAreaWB_mm2: 54.4544; Irms: 8.7A @ 40C rise; SizeArea_mm2: 28.9344; AEC Qualified: Y; AEC Category: Q200; Value: 2.2uH; SizeZ_mm: 3.1; Imax_A: 3.5A; AEC Grade: 1; SizeY_mm: 5.28; Isat: 2.5A @ 10% inductance drop; DCR_ohm: 0.012; SizeX_mm: 5.48
R30 = CRCW04024K42FKED: RES, 4.42 k, 1%, 0.063 W, 0402; Manufacturer: Vishay-Dale; CompType: Resistor; Value: 4.42k; Res_ohm: 4420; Value_Code: 4k42; Tolerance_%: 1; Power_W: 0.063; Value2: 0.063W; VDC_V: 50; TempCo: 100 ppm/C; SizeArea_mm2: 0.5; SizeZ_mm: 0.6; EIA_Code: E96; U/M: EA; AEC Category: Q200; Green_Lifecycle: Active; Green_REACh: Passed
R31 R111 R112 = CRCW04020000Z0ED: as R116 on sheet TIDA-010034 12V TO 5V TO POINT OF LOADS
R32 R37 R38 R40 R42 = CRCW040210K0FKED: RES, 10.0 k, 1%, 0.063 W, 0402; Manufacturer: Vishay-Dale; CompType: Resistor; Value: 10.0k; Res_ohm: 10000; Value_Code: 10k0; Tolerance_%: 1; Power_W: 0.063; Value2: 0.063W; VDC_V: 50; TempCo: 100 ppm/C; SizeArea_mm2: 0.5; SizeZ_mm: 0.6; EIA_Code: E96; U/M: EA; AEC Category: Q200; Green_Lifecycle: Active; Green_REACh: Passed
R33 = CRCW0402910RJNED: as R119 on sheet TIDA-010034 12V TO 5V TO POINT OF LOADS
R34 = CRCW12067R87FKEA: RES, 7.87, 1%, 0.25 W, 1206; Manufacturer: Vishay-Dale; CompType: Resistor; Value: 7.87; Value_Code: 7R87; Tolerance_%: 1; Power_W: 0.25; Value2: 0.25W; VDC_V: 200; TempCo: 100 ppm/C; SizeArea_mm2: 5.12; SizeX_mm: 3.2; SizeY_mm: 1.6; SizeZ_mm: 1.35; EIA_Code: E96; U/M: EA; AEC Category: Q200
R35 = CRCW04027K68FKED: RES, 7.68 k, 1%, 0.063 W, 0402; Manufacturer: Vishay-Dale; CompType: Resistor; Value: 7.68k; Res_ohm: 7680; Value_Code: 7k68; Tolerance_%: 1; Power_W: 0.063; Value2: 0.063W; VDC_V: 50; TempCo: 100 ppm/C; SizeArea_mm2: 0.5; SizeZ_mm: 0.6; EIA_Code: E96; U/M: EA; AEC Category: Q200; Green_Lifecycle: Active; Green_REACh: Passed
R36 = CRCW040256K2FKED: RES, 56.2 k, 1%, 0.063 W, 0402; Manufacturer: Vishay-Dale; CompType: Resistor; Value: 56.2k; Res_ohm: 56200; Value_Code: 56k2; Tolerance_%: 1; Power_W: 0.063; Value2: 0.063W; VDC_V: 50; TempCo: 100 ppm/C; SizeArea_mm2: 0.5; SizeZ_mm: 0.6; EIA_Code: E96; U/M: EA; AEC Category: Q200; Green_Lifecycle: Active; Green_REACh: Passed
R39 = CRCW040233K2FKED: RES, 33.2 k, 1%, 0.063 W, 0402; Manufacturer: Vishay-Dale; CompType: Resistor; Value: 33.2k; Res_ohm: 33200; Value_Code: 33k2; Tolerance_%: 1; Power_W: 0.063; Value2: 0.063W; VDC_V: 50; TempCo: 100 ppm/C; SizeArea_mm2: 0.5; SizeZ_mm: 0.6; EIA_Code: E96; U/M: EA; AEC Category: Q200
R41 = CRCW040213K3FKED: RES, 13.3 k, 1%, 0.063 W, 0402; Manufacturer: Vishay-Dale; CompType: Resistor; Value: 13.3k; Res_ohm: 13300; Value_Code: 13k3; Tolerance_%: 1; Power_W: 0.063; Value2: 0.063W; VDC_V: 50; TempCo: 100 ppm/C; SizeArea_mm2: 0.5; SizeZ_mm: 0.6; EIA_Code: E96; U/M: EA; AEC Category: Q200; Green_Lifecycle: Active; Green_REACh: Passed
R66-R68 = CRCW0402100KJNED: as R113 on sheet TIDA-010034 12V TO 5V TO POINT OF LOADS
U4 = TPS562208DDCR: 4.5V to 17V Input, 2A Output, Synchronous SWIFT Step-Down Converter, DDC0006A (SOT-23-T-6); Alternate PartNumber: TPS562208DDCT; Manufacturer: Texas Instruments; SymbolCreator: Altium; SizeArea_mm2: 4.8675; SizeAreaWB_mm2: 10.4675; SizeX_mm: 1.65; SizeY_mm: 2.95; SizeZ_mm: 0.87; CompType: IC; U/M: EA
U5 = TPS54201DDCR: as U31 on sheet TIDA-010034 12V TO 5V TO POINT OF LOADS
U6 = CMP-0013277-3: 4.5-V to 17-V Input, 2-A Synchronous Step-Down Voltage Regulator, DDC0006A (SOT-6); Alternate PartNumber: TPS561208DDCT; Manufacturer: Texas Instruments; SizeZ_mm: 0.87; SizeX_mm: 1.65; SizeY_mm: 2.95; SizeArea_mm2: 4.8675; CompType: IC; U/M: EA; SizeAreaWB_mm2: 10.4675
U7 U9 = TPS561201DDCR: 4.5-V to 17-V Input, 2-A Synchronous Step-Down Voltage Regulator, DDC0006A (SOT-23-T-6); Alternate PartNumber: TPS561201DDCT; Manufacturer: Texas Instruments; SymbolCreator: a0411947; SizeArea_mm2: 4.8675; SizeAreaWB_mm2: 10.4675; SizeX_mm: 1.65; SizeY_mm: 2.95; SizeZ_mm: 0.87; CompType: IC; U/M: EA
U8 = TPS562201DDCR: 4.5V to 17V Input, 2A Output, Synchronous Step-Down Converter, DDC0006A (SOT-23-T-6); Manufacturer: Texas Instruments; SymbolCreator: a0411947; SizeArea_mm2: 4.8675; SizeAreaWB_mm2: 10.4675; SizeX_mm: 1.65; SizeY_mm: 2.95; SizeZ_mm: 0.87; CompType: IC; U/M: EA; Green_Lifecycle: Active; Green_REACh: Passed
U18 = LM3880MF-1AA/NOPB: as U27 on sheet TIDA-010034 12V TO 5V TO POINT OF LOADS
U19 = CMP-0079107-2: as U26 on sheet TIDA-010034 12V TO 5V TO POINT OF LOADS
U20 = CMP-0079104-2: as U28 on sheet TIDA-010034 12V TO 5V TO POINT OF LOADS
U21 = CMP-0079101-2: as U29 on sheet TIDA-010034 12V TO 5V TO POINT OF LOADS
U22 = CMP-0079108-2: as U30 on sheet TIDA-010034 12V TO 5V TO POINT OF LOADS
